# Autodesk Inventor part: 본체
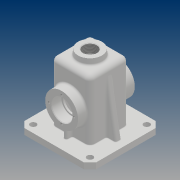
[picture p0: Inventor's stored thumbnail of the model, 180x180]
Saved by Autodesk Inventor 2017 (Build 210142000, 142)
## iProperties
Part Number: 본체
Material: 일반
Document SubType Name: Modeling
Designer: 20
Density: 1 g/cm^3
Appearance: 기본값
Mass: 293.223 g
Surface Area: 897.811 cm^2
Volume: 293.223 cm^3
Author: 20
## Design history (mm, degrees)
sketch "스케치1"
  geometry: L1 (-32.5, 32.5)-(32.5, 32.5); L2 (32.5, 32.5)-(32.5, -32.5); L3 (32.5, -32.5)-(-32.5, -32.5); L4 (-32.5, -32.5)-(-32.5, 32.5); L5 (-32.5, 32.5)-(32.5, -32.5); L6 (32.5, 32.5)-(-32.5, -32.5); 1 further point
  constraints: 12 end point, 2 midpoint, 2 parallel, 1 horizontal, 1 perpendicular
  dimensions: "d0" = 65 distance of L1.start L1.end; "d1" = 65 distance of L1.end L2.end
extrude "돌출1" new body sketch "스케치1" stored distance "d2" = 110; taper "d3" = 0 deg
fillet "모깎기1" dims "d4" = 8
fillet "모깎기2" dims "d5" = 8
feature "쉘1" dims "d6" = 5
sketch "스케치2"
  geometry: L1 (60, -60)-(-60, -60); L2 (-60, -60)-(-60, 60); L3 (-60, 60)-(60, 60); L4 (60, 60)-(60, -60); L5 (60, -60)-(-60, 60); L6 (-60, -60)-(60, 60); 1 further point
  constraints: 12 end point, 2 midpoint, 2 parallel, 1 horizontal, 1 perpendicular
  dimensions: "d7" = 120 distance of L1.start L1.end; "d8" = 120 distance of L1.end L2.end
extrude "돌출2" join sketch "스케치2" distance "d9" = 10; taper "d10" = 0 deg
sketch "스케치3"
  geometry: L1 (-27.5, -27.5)-(27.5, -27.5); L2 (27.5, -27.5)-(27.5, 27.5); L3 (27.5, 27.5)-(-27.5, 27.5); L4 (-27.5, 27.5)-(-27.5, -27.5); L5 (-27.5, -27.5)-(27.5, 27.5); L6 (27.5, -27.5)-(-27.5, 27.5); 1 further point
  constraints: 12 end point, 2 midpoint, 2 parallel, 1 horizontal, 1 perpendicular
  dimensions: "d11" = 55 distance of L2.end L3.end; "d12" = 55 distance of L3.end L1.start
extrude "돌출3" cut sketch "스케치3" distance "d13" = 10; taper "d14" = 0 deg
node "작업 평면1"
sketch "스케치4"
  geometry: C1 r 20 at (0, 0); 1 further point
  constraints: 1 centre point, 1 coincident
  dimensions: "d16" = 40 diameter of C1
extrude "돌출4" join sketch "스케치4" stored distance "d17" = 10; taper "d18" = 5 deg
hole "구멍1" diameter "d21" = 22.835; stored, may be unused: countersink angle "d25" = 90 deg, drill point angle "d27" = 118 deg; dims "d19" = 10, "d20" = 10, "d22" = 50, "d23" = 4, "d24" = 2, "d26" = 59.3
sketch "스케치5"
  geometry: L1 (84.5, -102)-(-35.5, -102) reference; C1 r 27.5 at (24.5, -47); 1 further point
  constraints: 1 centre point, 1 coincident
  dimensions: "d30" = 55 diameter of C1
extrude "돌출5" join sketch "스케치5" distance "d31" = 15; taper "d32" = 0 deg
sketch "스케치6" dims "d33" = 42
  geometry: 3 further points
  constraints: 2 vertical alignment, 1 coincident, 2 other
hole "구멍2" sketch "스케치6" at (0, 21) diameter "d34" = 3.242; stored, may be unused: countersink angle "d38" = 90 deg, drill point angle "d40" = 118 deg; dims "d35" = 8, "d36" = 4, "d37" = 2, "d39" = 10
sketch "스케치7"
  geometry: C1 r 17.5 at (0, 0); 1 further point
  constraints: 1 centre point, 1 coincident
  dimensions: "d44" = 35 diameter of C1
extrude "돌출6" cut sketch "스케치7" distance "d45" = 17; taper "d46" = 0 deg
sketch "스케치8"
  geometry: C1 r 15 at (0, 0); 1 further point
  constraints: 1 centre point, 1 coincident
  dimensions: "d47" = 30 diameter of C1
extrude "돌출7" cut sketch "스케치8" stored distance "d48" = 20; taper "d49" = 0 deg
sketch "스케치12"
  geometry: L1 (0, 84)-(0, -84) reference; L2 (-3, -42.5)-(3, -42.5); L3 (-27.5, -27.5)-(27.5, -27.5) reference; L4 (3, -42.5)-(3, -27.5); L5 (3, -27.5)-(-3, -27.5); L6 (-3, -27.5)-(-3, -42.5); 1 further point
  constraints: 8 end point, 2 point on line, 2 vertical
  dimensions: "d79" = 6 distance of L2.start L2.end; "d80" = 15 distance between parallel lines of L2 L3; "d81" = 3 horizontal distance of point (0, 0) L2.end
extrude "돌출10" join sketch "스케치12" stored distance "d82" = 6; taper "d83" = 0 deg; dims "d7" = 120, "d8" = 120, "d33" = 42, "d93" = 3
sketch "스케치10"
  geometry: L1 (-60, -45)-(60, -45) reference; L2 (-48, -45)-(-43.473, -19.328); L3 (-60, -55)-(-60, -45) reference; 1 further point
  constraints: 2 end point, 1 point on line
  dimensions: "d53" = 10 deg angle of L2 L3; "d54" = 12 distance from line of L2.start L3; "d55" = 25.67161 vertical distance of L2.start L2.end
feature "리브1" sketch "스케치10" dims "d56" = 1, "d57" = 10, "d58" = 0, "d59" = 0, "d60" = 1, "d61" = 1
chamfer "모따기3" distance "d105" = 10; stored, may be unused: second distance "d106" = 2, angle "d107" = 45 deg
sketch "스케치11"
  geometry: C1 r 5 at (-47.5, 47.5); C2 r 5 at (47.5, 47.5); C3 r 5 at (47.5, -47.5); C4 r 5 at (-47.5, -47.5); 1 further point
  constraints: 4 centre point, 2 horizontal alignment, 2 vertical alignment
  dimensions: "d65" = 10 diameter of C1; "d66" = 10 diameter of C2; "d67" = 10 diameter of C3; "d68" = 10 diameter of C4; "d69" = 95 distance of C4.centre C1.centre; "d70" = 95 distance of C2.centre C1.centre; "d71" = 47.5 horizontal distance of point (0, 0) C1.centre; "d72" = 47.5 horizontal distance of point (0, 0) C2.centre
extrude "돌출9" cut sketch "스케치11" stored distance "d73" = 6; taper "d74" = 0 deg
fillet "모깎기3" dims "d75" = 3
fillet "모깎기4" dims "d76" = 3
fillet "모깎기7" dims "d84" = 3
fillet "모깎기8" dims "d85" = 3
chamfer "모따기2" distance "d86" = 1; stored, may be unused: second distance "d87" = 2, angle "d88" = 45 deg
fillet "모깎기9" dims "d89" = 0.3
fillet "모깎기10" dims "d90" = 3
fillet "모깎기11" dims "d91" = 3
fillet "모깎기12" dims "d92" = 3
fillet "모깎기13" dims "d93" = 3
fillet "모깎기14" dims "d94" = 1
node "작업 평면3"
sketch "스케치14"
  geometry: L1 (57, 0)-(57, 91) reference; L2 (44.5, -18)-(4.5, -18) reference; 2 further points
  constraints: 1 other
  dimensions: "d101" = 32.5 distance from line of L1 point (24.5, 8); "d102" = 26 distance from line of L2 point (24.5, 8)
feature "엠보싱2" sketch "스케치14" dims "d103" = 0.5, "d104" = 0
node "솔리드1"
pattern_circular "원형 패턴1" dims angle "d42" = 360 deg
mirror "미러1"
mirror "미러4"
mirror "미러3"
